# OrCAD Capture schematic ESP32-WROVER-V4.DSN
size C; title: ESP32-WROVER-V4; rev: 1.0
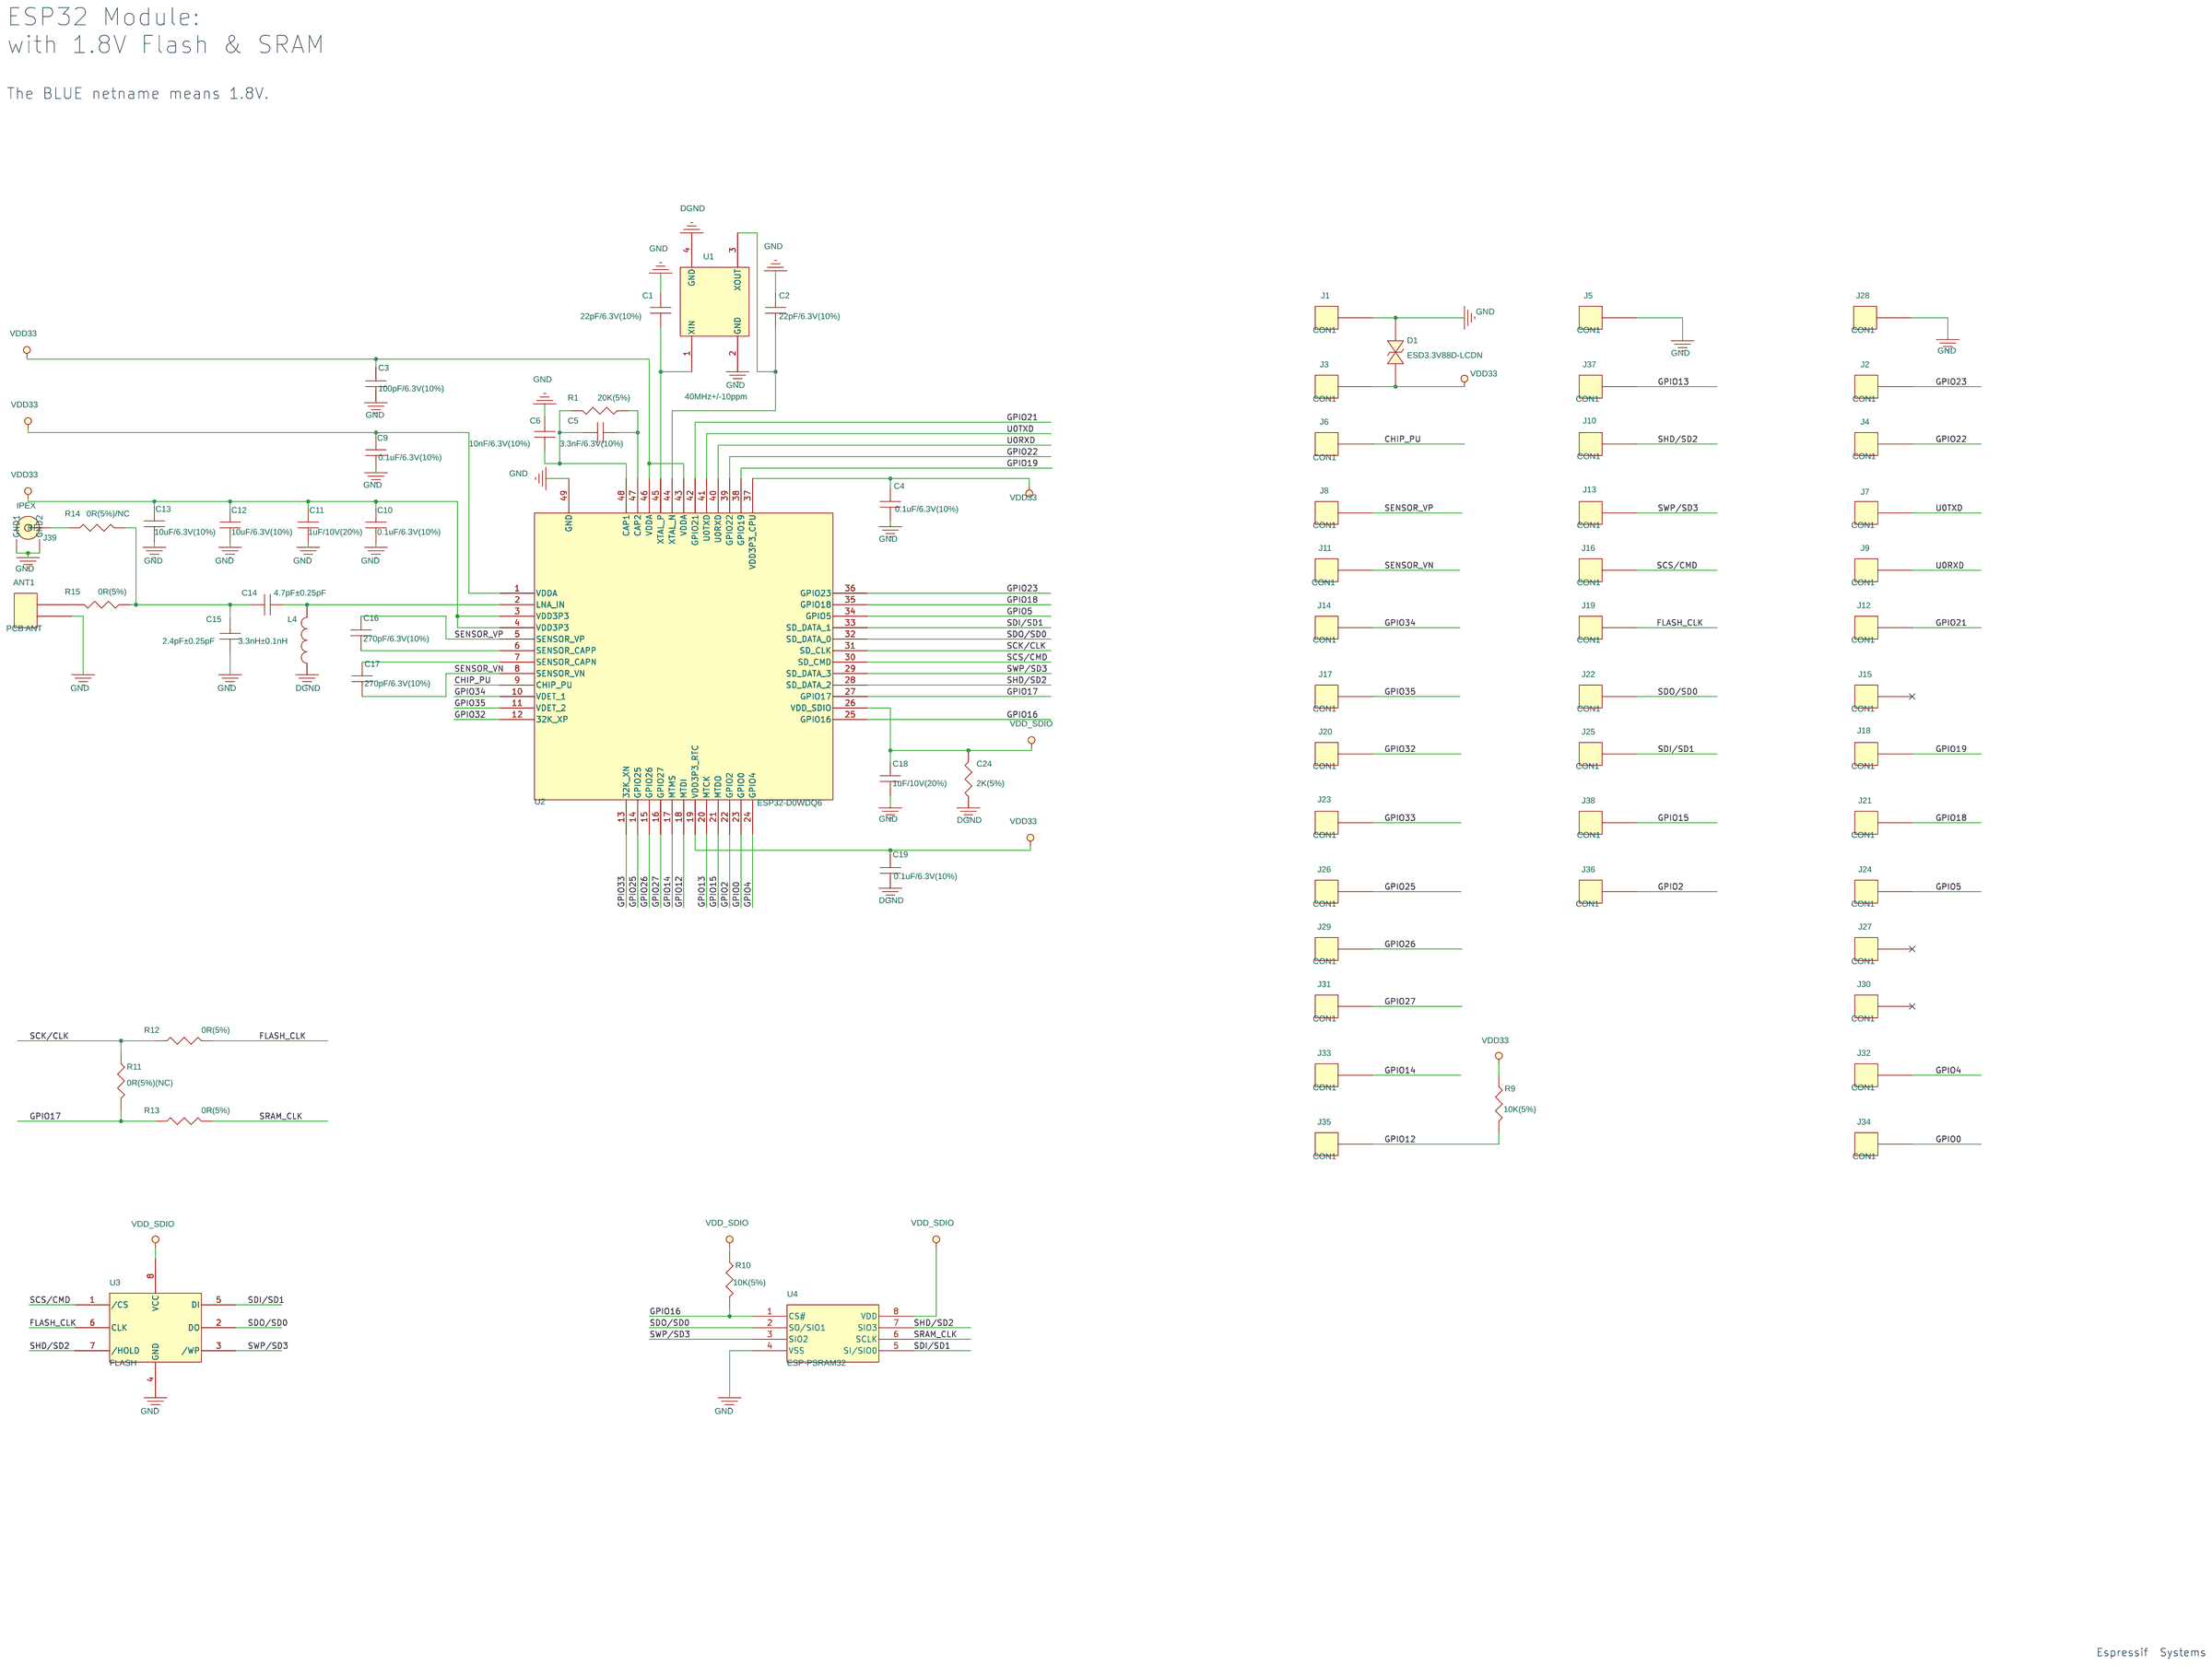
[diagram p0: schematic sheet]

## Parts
ANT1  PCB ANT  [MINI_ANT_TYPEA]
C1  22pF/6.3V(10%)  [C0402]
C2  22pF/6.3V(10%)  [C0402]
C3  100pF/6.3V(10%)  [C0402]
C4  0.1uF/6.3V(10%)  [C0402]
C5  3.3nF/6.3V(10%)  [C0402]
C6  10nF/6.3V(10%)  [C0402]
C9  0.1uF/6.3V(10%)  [C0402]
C10  0.1uF/6.3V(10%)  [C0402]
C11  1uF/10V(20%)  [C0603]
C12  10uF/6.3V(10%)  [C0603]
C13  10uF/6.3V(10%)  [C0603]
C14  4.7pF±0.25pF  [C0402]
C15  2.4pF±0.25pF  [C0402]
C16  270pF/6.3V(10%)  [C0402]
C17  270pF/6.3V(10%)  [C0402]
C18  1uF/10V(20%)  [C0603]
C19  0.1uF/6.3V(10%)  [C0402]
C24  2K(5%)  [R0402]
D1  ESD3.3V88D-LCDN  [SOD882]
J1  CON1  [SPAD_1]
J2  CON1  [SPAD_1]
J3  CON1  [SPAD_1]
J4  CON1  [SPAD_1]
J5  CON1  [SPAD_1]
J6  CON1  [SPAD_1]
J7  CON1  [SPAD_1]
J8  CON1  [SPAD_1]
J9  CON1  [SPAD_1]
J10  CON1  [SPAD_1]
J11  CON1  [SPAD_1]
J12  CON1  [SPAD_1]
J13  CON1  [SPAD_1]
J14  CON1  [SPAD_1]
J15  CON1  [SPAD_1]
J16  CON1  [SPAD_1]
J17  CON1  [SPAD_1]
J18  CON1  [SPAD_1]
J19  CON1  [SPAD_1]
J20  CON1  [SPAD_1]
J21  CON1  [SPAD_1]
J22  CON1  [SPAD_1]
J23  CON1  [SPAD_1]
J24  CON1  [SPAD_1]
J25  CON1  [SPAD_1]
J26  CON1  [SPAD_1]
J27  CON1  [SPAD_1]
J28  CON1  [SPAD_1]
J29  CON1  [SPAD_1]
J30  CON1  [SPAD_1]
J31  CON1  [SPAD_1]
J32  CON1  [SPAD_1]
J33  CON1  [SPAD_1]
J34  CON1  [SPAD_1]
J35  CON1  [SPAD_1]
J36  CON1  [SPAD_1]
J37  CON1  [SPAD_1]
J38  CON1  [SPAD_1]
J39  IPEX  [ECT818000368]
L4  3.3nH±0.1nH  [L0402]
R1  20K(5%)  [R0402]
R9  10K(5%)  [R0402]
R10  10K(5%)  [R0402]
R11  0R(5%)(NC)  [R0402]
R12  0R(5%)  [R0402]
R13  0R(5%)  [R0402]
R14  0R(5%)/NC  [R0402]
R15  0R(5%)  [R0402]
U1  40MHz+/-10ppm  [3225]
U2  ESP32-D0WDQ6  [QFN48]
U3  FLASH  [SOIC08]
U4  ESP-PSRAM32  [SOIC-8P]

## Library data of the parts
ANT1 = CON2
C1-C6 C9-C19 = CAP_NP
C24 R1 R9-R15 = RESISTOR
D1 = DIODE_BI-DIR_TRIG: Options: ESD
J1-J38 = CON1
J39 = IPEX_0
L4 = CHOKE
U1 = X1_1
U2 = ESP8080_33
U3 = FLASH_4
U4 = PN18S32

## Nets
GND: ANT1.2 C1.2 C2.2 C3.2 C4.2 C6.2 C9.2 C10.2 C11.2 C12.2 C13.2 C15.1 C18.2 C19.2 C24.1 D1.2 J1.1 J5.1 J28.1 J39.2(GND1) J39.3(GND2) L4.2 U1.2(GND) U1.4(GND) U2.49(GND) U3.4(GND) U4.4(VSS)
VDD33: C3.1 C4.1 C9.1 C10.1 C11.1 C12.1 C13.1 C19.1 D1.1 J3.1 R9.1 U2.1(VDDA) U2.3(VDD3P3) U2.4(VDD3P3) U2.19(VDD3P3_RTC) U2.37(VDD3P3_CPU) U2.43(VDDA) U2.46(VDDA)
VDD_SDIO: C18.1 C24.2 R10.1 U2.26(VDD_SDIO) U3.8(VCC) U4.8(VDD)
CHIP_PU: J6.1 U2.9(CHIP_PU)
FLASH_CLK: J19.1 R12.2 U3.6(CLK)
GPIO0: J34.1 U2.23(GPIO0)
GPIO2: J36.1 U2.22(GPIO2)
GPIO4: J32.1 U2.24(GPIO4)
GPIO5: J24.1 U2.34(GPIO5)
GPIO12: J35.1 R9.2 U2.18(MTDI)
GPIO13: J37.1 U2.20(MTCK)
GPIO14: J33.1 U2.17(MTMS)
GPIO15: J38.1 U2.21(MTDO)
GPIO16: R10.2 U2.25(GPIO16) U4.1(CS#)
GPIO17: R11.2 R13.1 U2.27(GPIO17)
GPIO18: J21.1 U2.35(GPIO18)
GPIO19: J18.1 U2.38(GPIO19)
GPIO21: J12.1 U2.42(GPIO21)
GPIO22: J4.1 U2.39(GPIO22)
GPIO23: J2.1 U2.36(GPIO23)
GPIO25: J26.1 U2.14(GPIO25)
GPIO26: J29.1 U2.15(GPIO26)
GPIO27: J31.1 U2.16(GPIO27)
GPIO32: J20.1 U2.12(32K_XP)
GPIO33: J23.1 U2.13(32K_XN)
GPIO34: J14.1 U2.10(VDET_1)
GPIO35: J17.1 U2.11(VDET_2)
SCK/CLK: R11.1 R12.1 U2.31(SD_CLK)
SCS/CMD: J16.1 U2.30(SD_CMD) U3.1(/CS)
SDI/SD1: J25.1 U2.33(SD_DATA_1) U3.5(DI) U4.5(SI/SIO0)
SDO/SD0: J22.1 U2.32(SD_DATA_0) U3.2(DO) U4.2(SO/SIO1)
SENSOR_VN: C17.2 J11.1 U2.8(SENSOR_VN)
SENSOR_VP: C16.1 J8.1 U2.5(SENSOR_VP)
SHD/SD2: J10.1 U2.28(SD_DATA_2) U3.7(/HOLD) U4.7(SIO3)
SRAM_CLK: R13.2 U4.6(SCLK)
SWP/SD3: J13.1 U2.29(SD_DATA_3) U3.3(/WP) U4.3(SIO2)
U0RXD: J9.1 U2.40(U0RXD)
U0TXD: J7.1 U2.41(U0TXD)
N16680176: C5.2 C6.1 R1.2 U2.48(CAP1)
N16680200: C14.2 C15.2 R14.2 R15.1
N16680240: ANT1.1 R15.2
N16680244: C2.1 U1.3(XOUT) U2.44(XTAL_N)
N16680316: C1.1 U1.1(XIN) U2.45(XTAL_P)
N16680402: C16.2 U2.6(SENSOR_CAPP)
N16680410: C17.1 U2.7(SENSOR_CAPN)
N16680558: C5.1 R1.1 U2.47(CAP2)
N16687029: C14.1 L4.1 U2.2(LNA_IN)
N16710353: J39.1(RF) R14.1

Not connected (* = marked no-connect by the designer): J15 1*; J27 1*; J30 1*

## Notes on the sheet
- ESP32 Module:
  with 1.8V Flash & SRAM
- The BLUE netname means 1.8V.
- Espressif  Systems
